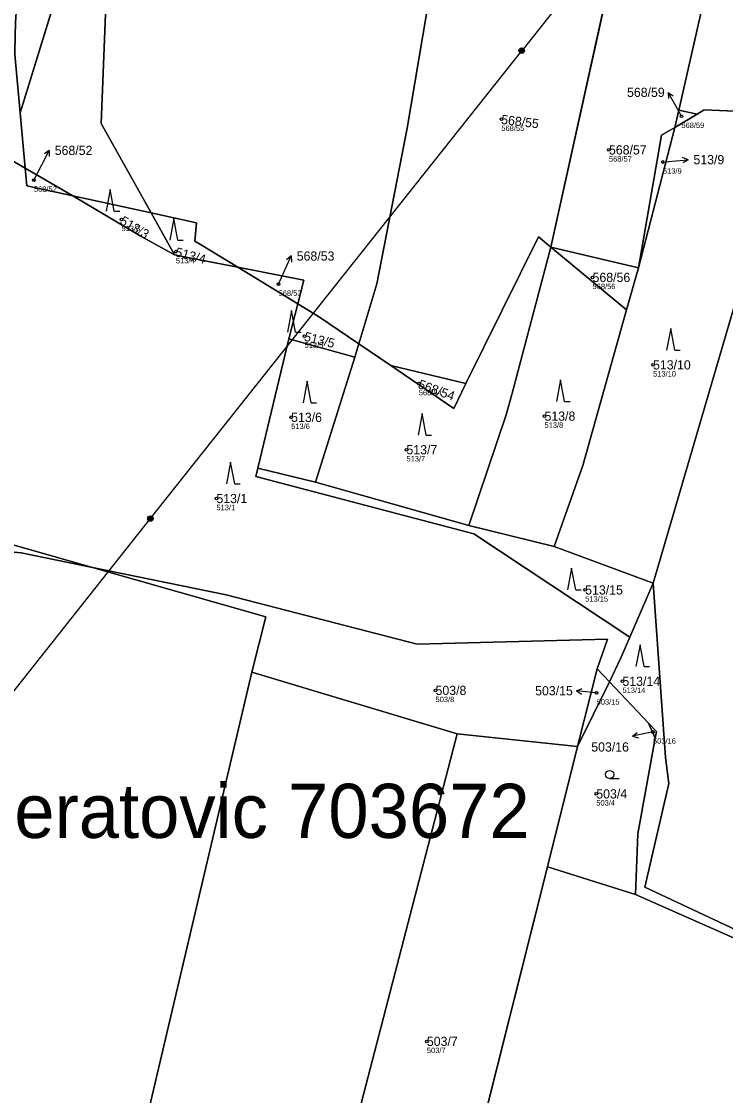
# Model space of a CAD drawing. Extents: x -732749 to -730903, y -1025757 to -1023435.
# Drawn here: x -731856.8 to -731726.8, y -1024539 to -1024340.6 of the extents above; entities that cross this region are included whole.
import ezdxf

# ---------------------------------------------------------------- set-up
doc = ezdxf.new("R2010")
doc.units = 0
for name, color, linetype in [('Definiční body', 7, 'Continuous'), ('Hranice parcel', 7, 'Continuous'), ('Parcelní čísla', 7, 'Continuous'), ('Polygon parcely', 7, 'Continuous'), ('Pop  PČ popisy', 7, 'Continuous'), ('Poz předměty', 7, 'Continuous'), ('Značky kultur', 7, 'Continuous')]:
    doc.layers.add(name, color=color, linetype=linetype)

msp = doc.modelspace()

# ---------------------------------------------------------------- linework, layer by layer
at = {"layer": 'Definiční body'}
for centre in [(-731734.96, -1024358.11), (-731768.2, -1024358.66), (-731748.33, -1024364.31), (-731738.37, -1024366.55), (-731854.5, -1024369.9), (-731838.34, -1024377.15), (-731828.3, -1024383.11), (-731751.36, -1024387.87), (-731809.33, -1024389.11), (-731804.53, -1024398.72), (-731740.19, -1024404.02), (-731783.44, -1024407.48), (-731807.01, -1024413.71), (-731760.23, -1024413.49), (-731785.72, -1024419.7), (-731820.81, -1024428.71), (-731752.72, -1024445.59), (-731745.84, -1024462.46), (-731780.35, -1024464.15), (-731750.61, -1024464.61), (-731740.2, -1024471.83), (-731750.67, -1024483.26), (-731781.95, -1024528.98)]:
    msp.add_circle(centre, 0.25, dxfattribs=at)
at = {"layer": 'Hranice parcel'}
for p, q in [((-731847.98, -1024328.06), (-731857.06, -1024357.44)), ((-731747.47, -1024329.77), (-731759.09, -1024382.25)), ((-731735.44, -1024356.95), (-731730.32, -1024334.42)), ((-731856.11, -1024367.69), (-731857.06, -1024357.44)), ((-731736.17, -1024360.15), (-731735.44, -1024356.95)), ((-731732.05, -1024357.71), (-731736.17, -1024360.15)), ((-731732.05, -1024357.71), (-731735.44, -1024356.95)), ((-731842.06, -1024359.44), (-731832.85, -1024375.95)), ((-731742.91, -1024386.11), (-731736.17, -1024360.15)), ((-731740.19, -1024444.33), (-731716.39, -1024363.19)), ((-731847.32, -1024372.79), (-731856.11, -1024367.69)), ((-731832.85, -1024375.95), (-731847.32, -1024372.79)), ((-731828.55, -1024383.67), (-731832.85, -1024375.95)), ((-731766.24, -1024409.49), (-731759.09, -1024382.25)), ((-731742.91, -1024386.11), (-731759.09, -1024382.25)), ((-731745.08, -1024393.87), (-731759.09, -1024382.25)), ((-731805.79, -1024392.73), (-731816.84, -1024386)), ((-731742.91, -1024386.11), (-731745.08, -1024393.87)), ((-731794.5, -1024400.13), (-731791.21, -1024389.06)), ((-731807.42, -1024399.21), (-731805.79, -1024392.73)), ((-731813.15, -1024423.07), (-731807.42, -1024399.21)), ((-731807.42, -1024399.21), (-731795.23, -1024402.57)), ((-731795.23, -1024402.57), (-731794.5, -1024400.13)), ((-731788.59, -1024404.16), (-731794.5, -1024400.13)), ((-731802.54, -1024425.69), (-731795.23, -1024402.57)), ((-731774.73, -1024407.46), (-731788.59, -1024404.16)), ((-731767.34, -1024413.23), (-731766.24, -1024409.49)), ((-731774.19, -1024433.69), (-731767.34, -1024413.23)), ((-731813.15, -1024423.07), (-731802.54, -1024425.69)), ((-731802.54, -1024425.69), (-731774.19, -1024433.69)), ((-731774.19, -1024433.69), (-731758.46, -1024437.59)), ((-731758.46, -1024437.59), (-731740.19, -1024444.33)), ((-731811.68, -1024450.53), (-731843.67, -1024441.44)), ((-731740.19, -1024444.33), (-731744.46, -1024454.32)), ((-731814.28, -1024460.77), (-731811.68, -1024450.53)), ((-731847.12, -1024600.4), (-731814.28, -1024460.77)), ((-731776.34, -1024472.18), (-731814.28, -1024460.77)), ((-731754.12, -1024474.53), (-731750.51, -1024460.16)), ((-731750.51, -1024460.16), (-731748.22, -1024462.58)), ((-731748.22, -1024462.58), (-731754.12, -1024474.53)), ((-731748.22, -1024462.58), (-731741.03, -1024470.21)), ((-731739.81, -1024473), (-731741.03, -1024470.21)), ((-731754.12, -1024474.53), (-731776.34, -1024472.18)), ((-731754.12, -1024474.53), (-731759.7, -1024496.71)), ((-731787.4, -1024607.01), (-731759.7, -1024496.71)), ((-731759.7, -1024496.71), (-731743.44, -1024501.87)), ((-731743.44, -1024501.87), (-731707.13, -1024517.89))]:
    msp.add_line(p, q, dxfattribs=at)
for points in [[(-731852.81, -1024217.16), (-731853.6, -1024246.75), (-731852.94, -1024254.38), (-731850.98, -1024269.43), (-731840.81, -1024326.71), (-731842.06, -1024359.44)], [(-731791.21, -1024389.06), (-731785.59, -1024360.29), (-731779.1, -1024322.02)], [(-731715.1, -1024357.61), (-731730.73, -1024356.93), (-731732.05, -1024357.71)], [(-731736.17, -1024360.15), (-731738.65, -1024361.61), (-731742.91, -1024386.11)], [(-731856.11, -1024367.69), (-731859.6, -1024365.67), (-731879.89, -1024430.93), (-731868.38, -1024434.41), (-731843.67, -1024441.44)], [(-731847.32, -1024372.79), (-731855.81, -1024370.93), (-731856.11, -1024367.69)], [(-731828.55, -1024383.67), (-731834.88, -1024380.17), (-731847.32, -1024372.79)], [(-731816.84, -1024386), (-731823.72, -1024381.81), (-731824.81, -1024381.15), (-731824.46, -1024377.79), (-731832.85, -1024375.95)], [(-731759.09, -1024382.25), (-731761.35, -1024380.37), (-731774.73, -1024407.46)], [(-731816.84, -1024386), (-731824.21, -1024384.55), (-731828.55, -1024383.67)], [(-731805.79, -1024392.73), (-731804.7, -1024388.39), (-731816.84, -1024386)], [(-731794.5, -1024400.13), (-731801.96, -1024395.06), (-731805.79, -1024392.73)], [(-731758.46, -1024437.59), (-731753.18, -1024422.6), (-731745.08, -1024393.87)], [(-731774.73, -1024407.46), (-731776.99, -1024412.05), (-731788.59, -1024404.16)], [(-731744.46, -1024454.32), (-731773.26, -1024435.22), (-731813.52, -1024424.64), (-731813.15, -1024423.07)], [(-731870.13, -1024438.76), (-731869.84, -1024438.72), (-731864.75, -1024438.03), (-731856.83, -1024438.73), (-731843.67, -1024441.44)], [(-731843.67, -1024441.44), (-731819.03, -1024446.5), (-731783.74, -1024455.6), (-731748.61, -1024454.67), (-731750.51, -1024460.16)], [(-731740.19, -1024444.33), (-731737.87, -1024476.57), (-731737.29, -1024481.37), (-731741.71, -1024500.51), (-731722.91, -1024509.3)], [(-731748.22, -1024462.58), (-731746.1, -1024457.98), (-731744.46, -1024454.32)], [(-731741.03, -1024470.21), (-731739.58, -1024471.75), (-731739.81, -1024473)], [(-731808.81, -1024602.42), (-731796.96, -1024551.61), (-731776.34, -1024472.18)], [(-731739.81, -1024473), (-731743, -1024490.66), (-731743.44, -1024501.87)]]:
    msp.add_lwpolyline(points, dxfattribs=at)
at = {"layer": 'Polygon parcely'}
for points in [[(-731861.81, -1024215.51), (-731862.57, -1024232.86), (-731861.58, -1024252.76), (-731857.16, -1024282.16), (-731851.12, -1024308.49), (-731847.98, -1024328.06), (-731857.06, -1024357.44), (-731856.11, -1024367.69), (-731847.32, -1024372.79), (-731832.85, -1024375.95), (-731842.06, -1024359.44), (-731840.81, -1024326.71), (-731850.98, -1024269.43), (-731852.94, -1024254.38), (-731853.6, -1024246.75), (-731852.81, -1024217.16)], [(-731856.96, -1024303.62), (-731857.08, -1024308.4), (-731855.49, -1024319.02), (-731854.66, -1024329.36), (-731857.86, -1024339.43), (-731857.95, -1024342.94), (-731858.05, -1024346.7), (-731857.06, -1024357.44), (-731847.98, -1024328.06), (-731851.12, -1024308.49), (-731857.16, -1024282.16), (-731861.58, -1024252.76), (-731862.57, -1024232.86), (-731863.42, -1024252.13), (-731859.75, -1024276.86)], [(-731794.5, -1024400.13), (-731788.59, -1024404.16), (-731774.73, -1024407.46), (-731761.35, -1024380.37), (-731759.09, -1024382.25), (-731747.47, -1024329.77), (-731770.57, -1024324.47), (-731779.1, -1024322.02), (-731785.59, -1024360.29), (-731791.21, -1024389.06)], [(-731730.32, -1024334.42), (-731742.25, -1024330.96), (-731747.47, -1024329.77), (-731759.09, -1024382.25), (-731742.91, -1024386.11), (-731738.65, -1024361.61), (-731736.17, -1024360.15), (-731735.44, -1024356.95)], [(-731715.1, -1024357.61), (-731710.83, -1024339.62), (-731715.01, -1024338.86), (-731730.32, -1024334.42), (-731735.44, -1024356.95), (-731732.05, -1024357.71), (-731730.73, -1024356.93)], [(-731716.39, -1024363.19), (-731715.1, -1024357.61), (-731730.73, -1024356.93), (-731732.05, -1024357.71), (-731736.17, -1024360.15), (-731742.91, -1024386.11), (-731745.08, -1024393.87), (-731753.18, -1024422.6), (-731758.46, -1024437.59), (-731740.19, -1024444.33)], [(-731732.05, -1024357.71), (-731735.44, -1024356.95), (-731736.17, -1024360.15)], [(-731742.91, -1024386.11), (-731736.17, -1024360.15), (-731738.65, -1024361.61)], [(-731721.04, -1024455.23), (-731697.25, -1024368.6), (-731716.39, -1024363.19), (-731740.19, -1024444.33), (-731737.87, -1024476.57), (-731737.29, -1024481.37), (-731741.71, -1024500.51), (-731722.91, -1024509.3), (-731719.02, -1024493.81)], [(-731744.46, -1024454.32), (-731773.26, -1024435.22), (-731813.52, -1024424.64), (-731813.15, -1024423.07), (-731807.42, -1024399.21), (-731805.79, -1024392.73), (-731816.84, -1024386), (-731824.21, -1024384.55), (-731828.55, -1024383.67), (-731834.88, -1024380.17), (-731847.32, -1024372.79), (-731855.81, -1024370.93), (-731856.11, -1024367.69), (-731859.6, -1024365.67), (-731879.89, -1024430.93), (-731868.38, -1024434.41), (-731843.67, -1024441.44), (-731819.03, -1024446.5), (-731783.74, -1024455.6), (-731748.61, -1024454.67), (-731750.51, -1024460.16), (-731748.22, -1024462.58), (-731746.1, -1024457.98)], [(-731847.32, -1024372.79), (-731856.11, -1024367.69), (-731855.81, -1024370.93)], [(-731832.85, -1024375.95), (-731847.32, -1024372.79), (-731834.88, -1024380.17), (-731828.55, -1024383.67)], [(-731824.81, -1024381.15), (-731824.46, -1024377.79), (-731832.85, -1024375.95), (-731828.55, -1024383.67), (-731824.21, -1024384.55), (-731816.84, -1024386), (-731823.72, -1024381.81)], [(-731759.09, -1024382.25), (-731761.35, -1024380.37), (-731774.73, -1024407.46), (-731776.99, -1024412.05), (-731788.59, -1024404.16), (-731794.5, -1024400.13), (-731795.23, -1024402.57), (-731802.54, -1024425.69), (-731774.19, -1024433.69), (-731767.34, -1024413.23), (-731766.24, -1024409.49)], [(-731758.46, -1024437.59), (-731753.18, -1024422.6), (-731745.08, -1024393.87), (-731759.09, -1024382.25), (-731766.24, -1024409.49), (-731767.34, -1024413.23), (-731774.19, -1024433.69)], [(-731759.09, -1024382.25), (-731745.08, -1024393.87), (-731742.91, -1024386.11)], [(-731805.79, -1024392.73), (-731804.7, -1024388.39), (-731816.84, -1024386)], [(-731794.5, -1024400.13), (-731801.96, -1024395.06), (-731805.79, -1024392.73), (-731807.42, -1024399.21), (-731795.23, -1024402.57)], [(-731795.23, -1024402.57), (-731807.42, -1024399.21), (-731813.15, -1024423.07), (-731802.54, -1024425.69)], [(-731774.73, -1024407.46), (-731788.59, -1024404.16), (-731776.99, -1024412.05)], [(-731813.15, -1024423.07), (-731813.52, -1024424.64), (-731773.26, -1024435.22), (-731744.46, -1024454.32), (-731740.19, -1024444.33), (-731758.46, -1024437.59), (-731774.19, -1024433.69), (-731802.54, -1024425.69)], [(-731895.85, -1024517.94), (-731900.98, -1024539.52), (-731912.24, -1024588.03), (-731911.71, -1024588.16), (-731886.13, -1024594.36), (-731862.59, -1024598.65), (-731847.12, -1024600.4), (-731814.28, -1024460.77), (-731811.68, -1024450.53), (-731843.67, -1024441.44), (-731856.83, -1024438.73), (-731864.75, -1024438.03), (-731869.84, -1024438.72), (-731870.13, -1024438.76)], [(-731754.12, -1024474.53), (-731750.51, -1024460.16), (-731748.61, -1024454.67), (-731783.74, -1024455.6), (-731819.03, -1024446.5), (-731843.67, -1024441.44), (-731811.68, -1024450.53), (-731814.28, -1024460.77), (-731776.34, -1024472.18)], [(-731740.19, -1024444.33), (-731744.46, -1024454.32), (-731746.1, -1024457.98), (-731748.22, -1024462.58), (-731741.03, -1024470.21), (-731739.58, -1024471.75), (-731739.81, -1024473), (-731743, -1024490.66), (-731743.44, -1024501.87), (-731707.13, -1024517.89), (-731722.91, -1024509.3), (-731741.71, -1024500.51), (-731737.29, -1024481.37), (-731737.87, -1024476.57)], [(-731776.34, -1024472.18), (-731814.28, -1024460.77), (-731847.12, -1024600.4), (-731837.21, -1024601.53), (-731833.13, -1024601.99), (-731808.81, -1024602.42), (-731796.96, -1024551.61)], [(-731748.22, -1024462.58), (-731750.51, -1024460.16), (-731754.12, -1024474.53)], [(-731748.22, -1024462.58), (-731754.12, -1024474.53), (-731759.7, -1024496.71), (-731743.44, -1024501.87), (-731743, -1024490.66), (-731739.81, -1024473), (-731741.03, -1024470.21)], [(-731739.81, -1024473), (-731739.58, -1024471.75), (-731741.03, -1024470.21)], [(-731787.4, -1024607.01), (-731759.7, -1024496.71), (-731754.12, -1024474.53), (-731776.34, -1024472.18), (-731796.96, -1024551.61), (-731808.81, -1024602.42), (-731802.86, -1024602.52), (-731788.85, -1024604.19), (-731789.72, -1024606.52)], [(-731707.13, -1024517.89), (-731743.44, -1024501.87), (-731759.7, -1024496.71), (-731787.4, -1024607.01), (-731752.45, -1024614.47), (-731732.6, -1024618.66), (-731734.11, -1024625.8), (-731735.24, -1024629.79), (-731736, -1024632.96), (-731734.05, -1024633.47), (-731713.45, -1024547.12)]]:
    msp.add_lwpolyline(points, close=True, dxfattribs=at)
for points in [[(-731840.81, -1024326.71), (-731842.06, -1024359.44), (-731832.85, -1024375.95), (-731824.46, -1024377.79), (-731824.81, -1024381.15), (-731823.72, -1024381.81), (-731816.84, -1024386), (-731804.7, -1024388.39), (-731805.79, -1024392.73), (-731801.96, -1024395.06), (-731794.5, -1024400.13), (-731791.21, -1024389.06), (-731785.59, -1024360.29), (-731779.1, -1024322.02)], [(-731860.33, -1024327.98), (-731863.67, -1024352.15), (-731867.73, -1024368.19), (-731868.71, -1024373.56), (-731870.29, -1024382.22), (-731875.55, -1024411.06), (-731881.84, -1024438.85), (-731883.41, -1024448.1), (-731882.01, -1024454.65), (-731872.45, -1024439.07), (-731870.13, -1024438.76), (-731869.84, -1024438.72), (-731864.75, -1024438.03), (-731856.83, -1024438.73), (-731843.67, -1024441.44), (-731868.38, -1024434.41), (-731879.89, -1024430.93), (-731859.6, -1024365.67), (-731856.11, -1024367.69), (-731857.06, -1024357.44), (-731858.05, -1024346.7), (-731857.95, -1024342.94), (-731857.86, -1024339.43)]]:
    msp.add_lwpolyline(points, dxfattribs=at)
at = {"layer": 'Pop  PČ popisy'}
for p, q in [((-731735.95, -1024356.31), (-731737.41, -1024353.69)), ((-731737.41, -1024353.69), (-731736.48, -1024354.32)), ((-731737.41, -1024353.69), (-731737.36, -1024354.8)), ((-731734.96, -1024358.11), (-731735.95, -1024356.31)), ((-731853.04, -1024367.07), (-731851.68, -1024364.4)), ((-731851.68, -1024364.4), (-731852.58, -1024365.06)), ((-731851.68, -1024364.4), (-731851.69, -1024365.52)), ((-731733.73, -1024366.13), (-731734.77, -1024365.72)), ((-731854.5, -1024369.9), (-731853.04, -1024367.07)), ((-731738.37, -1024366.55), (-731736.72, -1024366.39)), ((-731736.72, -1024366.39), (-731733.73, -1024366.13)), ((-731733.73, -1024366.13), (-731734.68, -1024366.71)), ((-731808.22, -1024386.65), (-731807, -1024383.91)), ((-731807, -1024383.91), (-731807.86, -1024384.62)), ((-731807, -1024383.91), (-731806.95, -1024385.03)), ((-731809.33, -1024389.11), (-731808.22, -1024386.65)), ((-731754.35, -1024464.22), (-731753.31, -1024463.82)), ((-731751.37, -1024464.53), (-731754.35, -1024464.22)), ((-731754.35, -1024464.22), (-731753.41, -1024464.82)), ((-731750.61, -1024464.61), (-731751.37, -1024464.53)), ((-731743.98, -1024472.63), (-731743.11, -1024471.94)), ((-731741.05, -1024472.01), (-731743.98, -1024472.63)), ((-731743.98, -1024472.63), (-731742.9, -1024472.92)), ((-731740.2, -1024471.83), (-731741.05, -1024472.01))]:
    msp.add_line(p, q, dxfattribs=at)
at = {"layer": 'Poz předměty'}
for p, q in [((-731632.07, -1024179.24), (-731764.45, -1024345.99)), ((-731832.99, -1024432.41), (-731764.45, -1024345.99)), ((-731902.98, -1024520.72), (-731832.99, -1024432.41))]:
    msp.add_line(p, q, dxfattribs=at)
for centre, radius in [((-731764.45, -1024345.99), 0.5), ((-731764.45, -1024345.99), 0.4), ((-731764.45, -1024345.99), 0.3), ((-731764.45, -1024345.99), 0.2), ((-731764.45, -1024345.99), 0.1), ((-731832.99, -1024432.41), 0.5), ((-731832.99, -1024432.41), 0.4), ((-731832.99, -1024432.41), 0.3), ((-731832.99, -1024432.41), 0.2), ((-731832.99, -1024432.41), 0.1)]:
    msp.add_circle(centre, radius, dxfattribs=at)
at = {"layer": 'Značky kultur'}
for p, q in [((-731840.42, -1024371.62), (-731841.17, -1024375.62)), ((-731839.67, -1024375.62), (-731840.42, -1024371.62)), ((-731839.67, -1024375.62), (-731838.67, -1024375.62)), ((-731828.68, -1024377.01), (-731829.43, -1024381.01)), ((-731827.93, -1024381.01), (-731828.68, -1024377.01)), ((-731827.93, -1024381.01), (-731826.93, -1024381.01)), ((-731806.94, -1024393.99), (-731807.69, -1024397.99)), ((-731806.19, -1024397.99), (-731806.94, -1024393.99)), ((-731736.93, -1024397.32), (-731737.68, -1024401.32)), ((-731736.18, -1024401.32), (-731736.93, -1024397.32)), ((-731806.19, -1024397.99), (-731805.19, -1024397.99)), ((-731736.18, -1024401.32), (-731735.18, -1024401.32)), ((-731804.07, -1024407.01), (-731804.82, -1024411.01)), ((-731803.32, -1024411.01), (-731804.07, -1024407.01)), ((-731757.27, -1024406.79), (-731758.02, -1024410.79)), ((-731756.52, -1024410.79), (-731757.27, -1024406.79)), ((-731803.32, -1024411.01), (-731802.32, -1024411.01)), ((-731756.52, -1024410.79), (-731755.52, -1024410.79)), ((-731782.82, -1024413), (-731783.57, -1024417)), ((-731782.07, -1024417), (-731782.82, -1024413)), ((-731782.07, -1024417), (-731781.07, -1024417)), ((-731818.18, -1024422.01), (-731818.93, -1024426.01)), ((-731817.43, -1024426.01), (-731818.18, -1024422.01)), ((-731817.43, -1024426.01), (-731816.43, -1024426.01)), ((-731755.22, -1024441.59), (-731755.97, -1024445.59)), ((-731754.47, -1024445.59), (-731755.22, -1024441.59)), ((-731754.47, -1024445.59), (-731753.47, -1024445.59)), ((-731742.6, -1024455.76), (-731743.35, -1024459.76)), ((-731741.85, -1024459.76), (-731742.6, -1024455.76)), ((-731741.85, -1024459.76), (-731740.85, -1024459.76)), ((-731748.21, -1024480.43), (-731746.46, -1024480.43))]:
    msp.add_line(p, q, dxfattribs=at)
msp.add_circle((-731748.21, -1024479.68), 0.75, dxfattribs=at)

# ---------------------------------------------------------------- texts
at = {"layer": 'Definiční body'}
for s, p in [('568/55', (-731768.2, -1024360.82)), ('568/59', (-731734.96, -1024360.27)), ('568/57', (-731748.33, -1024366.47)), ('513/9', (-731738.37, -1024368.71)), ('568/52', (-731854.5, -1024372.06)), ('513/3', (-731838.34, -1024379.31)), ('513/4', (-731828.3, -1024385.27)), ('568/56', (-731751.36, -1024390.03)), ('568/53', (-731809.33, -1024391.27)), ('513/5', (-731804.53, -1024400.88)), ('513/10', (-731740.19, -1024406.18)), ('568/54', (-731783.44, -1024409.64)), ('513/6', (-731807.01, -1024415.87)), ('513/8', (-731760.23, -1024415.65)), ('513/7', (-731785.72, -1024421.86)), ('513/1', (-731820.81, -1024430.87)), ('513/15', (-731752.72, -1024447.75)), ('513/14', (-731745.84, -1024464.62)), ('503/8', (-731780.35, -1024466.31)), ('503/15', (-731750.61, -1024466.77)), ('503/16', (-731740.2, -1024473.99)), ('503/4', (-731750.67, -1024485.42)), ('503/7', (-731781.95, -1024531.14))]:
    msp.add_text(s, height=1, dxfattribs=at).set_placement(p)
at = {"layer": 'Parcelní čísla'}
for s, p in [('568/59', (-731745, -1024354.53)), ('568/52', (-731850.66, -1024365.26)), ('568/57', (-731748.33, -1024365.16)), ('513/9', (-731732.73, -1024366.96)), ('568/53', (-731805.98, -1024384.77)), ('568/56', (-731751.36, -1024388.72)), ('513/10', (-731740.19, -1024404.87)), ('513/6', (-731807.01, -1024414.56)), ('513/8', (-731760.23, -1024414.34)), ('513/7', (-731785.72, -1024420.55)), ('513/1', (-731820.81, -1024429.56)), ('513/15', (-731752.72, -1024446.44)), ('513/14', (-731745.84, -1024463.31)), ('503/8', (-731780.35, -1024465)), ('503/15', (-731761.96, -1024465.06)), ('503/16', (-731751.6, -1024475.44)), ('503/4', (-731750.67, -1024484.11)), ('503/7', (-731781.95, -1024529.83))]:
    msp.add_text(s, height=1.7, dxfattribs=at).set_placement(p)
for s, rotation, p in [('568/55', 353, (-731768.3, -1024359.5)), ('513/3', 329, (-731838.78, -1024377.88)), ('513/4', 345, (-731828.52, -1024383.93)), ('513/5', 346, (-731804.73, -1024399.54)), ('568/54', 340, (-731783.73, -1024408.28))]:
    msp.add_text(s, height=1.7, rotation=rotation, dxfattribs=at).set_placement(p)
at = {"layer": 'Pop  PČ popisy'}
msp.add_text('Mlékojedy u Neratovic 703672', height=10, dxfattribs=at).set_placement((-731942.85, -1024491.4))

doc.saveas('drawing.dxf')
